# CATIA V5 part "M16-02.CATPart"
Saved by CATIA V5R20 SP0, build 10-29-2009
Part number: M16-02
Revision: ANY
Definition: UNKNOWN
Nomenclature: M16-02
Source: Unknown
Bounding box of the stored display mesh (mm): x -11 to 11, y -10.833 to 10.833, z 0 to 170
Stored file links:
  C:\Users\Utente\Desktop\IO LAVORO\3D X SITO CF\X 3D SITO CF 27-09-2020\740T\M16-02.CATPart
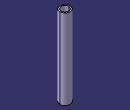
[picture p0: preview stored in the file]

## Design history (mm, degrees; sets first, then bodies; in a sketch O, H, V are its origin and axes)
Body1 "NONE" (main body)
  Solid1: solid without history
